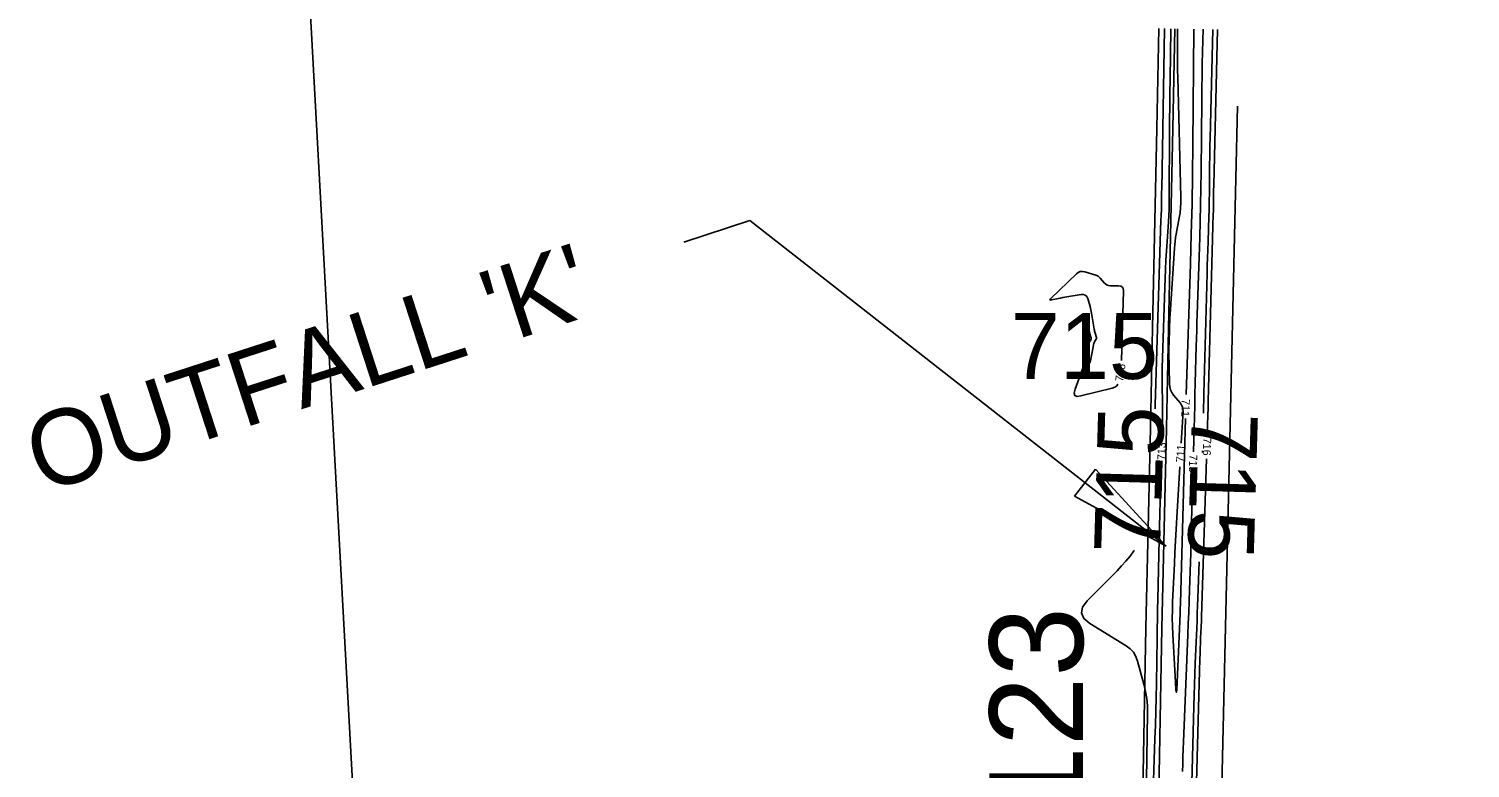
# Model space of a CAD drawing. Extents: x -468563856 to 36492962, y -306094093 to 11899197.
# Drawn here: x 1818576 to 1819296, y 531590 to 531960 of the extents above; entities that cross this region are included whole.
import ezdxf

# ---------------------------------------------------------------- set-up
doc = ezdxf.new("R2010")
doc.units = 0
for name, color, linetype in [('DT_X_Contour_Minor', 7, 'Continuous'), ('DT_X_Terrain_Boundary', 7, 'Continuous'), ('Level 19', 7, 'Continuous'), ('Level 40', 7, 'Continuous'), ('Level 56', 7, 'Continuous'), ('SC_Scratch1', 7, 'Continuous')]:
    doc.layers.add(name, color=color, linetype=linetype)

msp = doc.modelspace()

# ---------------------------------------------------------------- linework, layer by layer
at = {"layer": 'DT_X_Contour_Minor'}
for points in [[(1819138.66, 531769.93), (1819138.65, 531770.63), (1819138.65, 531770.93), (1819138.65, 531771.23), (1819138.66, 531771.53), (1819138.66, 531771.83), (1819141.51, 531864.46), (1819141.53, 531865.12), (1819141.56, 531865.78), (1819141.59, 531866.44), (1819141.63, 531867.1), (1819141.77, 531869.25), (1819141.8, 531869.71), (1819141.82, 531870.17), (1819141.83, 531870.63), (1819141.84, 531871.09), (1819141.85, 531875.68), (1819141.86, 531876.66), (1819141.86, 531877.64), (1819141.88, 531878.62), (1819141.89, 531879.61), (1819143.26, 531960.15)], [(1819142, 531754.87), (1819142.17, 531760.74), (1819142.24, 531763.67), (1819142.28, 531766.6), (1819142.29, 531769.53), (1819142.26, 531772.45), (1819142.13, 531782.02), (1819142.11, 531784.07), (1819142.12, 531786.12), (1819142.15, 531788.17), (1819142.2, 531790.22), (1819143.44, 531830.59), (1819143.6, 531835.12), (1819143.8, 531839.66), (1819144.03, 531844.18), (1819144.31, 531848.71), (1819145.27, 531863.49), (1819145.45, 531866.66), (1819145.58, 531869.83), (1819145.67, 531873.01), (1819145.7, 531876.18), (1819145.81, 531907.73), (1819145.85, 531914.49), (1819145.9, 531921.25), (1819145.98, 531928.02), (1819146.09, 531934.78), (1819146.51, 531959.67), (1819146.51, 531959.94)], [(1819149.84, 531960), (1819149.8, 531949.14), (1819149.8, 531945.84), (1819149.83, 531942.54), (1819149.87, 531939.23), (1819149.94, 531935.93), (1819151.45, 531875.54), (1819151.44, 531873), (1819151.31, 531870.48), (1819151.05, 531867.96), (1819150.65, 531865.45), (1819149.15, 531857.27), (1819148.85, 531855.51), (1819148.61, 531853.75), (1819148.42, 531851.98), (1819148.28, 531850.21), (1819146.13, 531817.29), (1819146.02, 531815.41), (1819145.92, 531813.54), (1819145.84, 531811.66), (1819145.77, 531809.78), (1819145.58, 531803.64), (1819145.55, 531802.32), (1819145.53, 531801.01), (1819145.53, 531799.69), (1819145.54, 531798.38), (1819145.76, 531782.47), (1819145.91, 531780.9), (1819146.31, 531779.42), (1819146.96, 531778.04), (1819147.87, 531776.74), (1819151.24, 531772.67), (1819151.86, 531771.77), (1819152.29, 531770.8), (1819152.52, 531769.76), (1819152.55, 531768.66), (1819151.63, 531752.75)], [(1819154.07, 531777.06), (1819156.25, 531842.45), (1819156.7, 531857.35), (1819157.06, 531872.26), (1819157.32, 531887.16), (1819157.49, 531902.07), (1819157.98, 531959.85)], [(1819157.77, 531748.32), (1819158.08, 531760.02), (1819158.23, 531765.69), (1819158.38, 531771.35), (1819158.53, 531777.01), (1819158.68, 531782.67), (1819159.16, 531801.17), (1819159.27, 531805.14), (1819159.38, 531809.1), (1819159.5, 531813.06), (1819159.63, 531817.02), (1819160.91, 531855.52), (1819161.16, 531863.77), (1819161.36, 531872.02), (1819161.51, 531880.28), (1819161.6, 531888.53), (1819161.9, 531924.54), (1819161.97, 531930.53), (1819162.05, 531936.51), (1819162.16, 531942.49), (1819162.3, 531948.47), (1819162.57, 531959.76)], [(1819162.78, 531767.67), (1819162.86, 531770.9), (1819162.95, 531774.2), (1819163.04, 531777.49), (1819164.6, 531837.59), (1819164.71, 531841.54), (1819164.82, 531845.49), (1819164.94, 531849.43), (1819165.07, 531853.38), (1819165.5, 531866.27), (1819165.58, 531869.03), (1819165.65, 531871.79), (1819165.7, 531874.56), (1819165.73, 531877.32), (1819165.86, 531892.32), (1819165.89, 531895.54), (1819165.94, 531898.75), (1819166, 531901.97), (1819166.07, 531905.18), (1819167.4, 531959.66)], [(1819164.73, 531756.92), (1819164.78, 531758.61), (1819164.84, 531760.74), (1819165.03, 531767.7), (1819165.07, 531769.19), (1819165.11, 531770.68), (1819165.14, 531772.17), (1819165.18, 531773.66), (1819167.47, 531861.28), (1819167.5, 531862.48), (1819167.53, 531863.68), (1819167.57, 531864.88), (1819167.61, 531866.08), (1819167.74, 531870), (1819167.77, 531870.84), (1819167.79, 531871.68), (1819167.8, 531872.52), (1819167.81, 531873.36), (1819167.85, 531877.92), (1819167.86, 531878.9), (1819167.87, 531879.87), (1819167.89, 531880.85), (1819167.91, 531881.83), (1819169.82, 531959.61)], [(1819121.77, 531793.97), (1819122.82, 531828.9), (1819122.7, 531830.01), (1819122.25, 531830.8), (1819121.47, 531831.28), (1819120.36, 531831.44), (1819116.22, 531831.46), (1819115.37, 531831.54), (1819114.6, 531831.8), (1819113.9, 531832.22), (1819113.29, 531832.81), (1819111.16, 531835.28), (1819110.68, 531835.77), (1819110.14, 531836.17), (1819109.55, 531836.5), (1819108.91, 531836.74), (1819103.39, 531838.42), (1819102.25, 531838.63), (1819101.18, 531838.54), (1819100.18, 531838.13), (1819099.25, 531837.43), (1819086.49, 531825.13), (1819086.11, 531824.69), (1819086.05, 531824.42), (1819086.3, 531824.32), (1819086.88, 531824.39)], [(1819086.88, 531824.39), (1819090.31, 531825.09), (1819091.36, 531825.3), (1819092.42, 531825.5), (1819093.47, 531825.69), (1819094.53, 531825.87), (1819101.69, 531827.04), (1819102.82, 531827.07), (1819103.72, 531826.75), (1819104.42, 531826.08), (1819104.89, 531825.05), (1819106.08, 531821.14), (1819106.32, 531820.3), (1819106.53, 531819.45), (1819106.71, 531818.6), (1819106.87, 531817.74), (1819108.17, 531809.81), (1819108.26, 531809.3), (1819108.37, 531808.79), (1819108.48, 531808.28), (1819108.61, 531807.77), (1819109.22, 531805.52), (1819109.23, 531805.47), (1819109.24, 531805.43), (1819109.26, 531805.38), (1819109.27, 531805.33), (1819109.32, 531805.19), (1819109.32, 531805.16), (1819109.32, 531805.13), (1819109.32, 531805.1), (1819109.3, 531805.07), (1819108.34, 531803.34), (1819108.15, 531802.97), (1819107.99, 531802.58), (1819107.87, 531802.18), (1819107.78, 531801.77), (1819106.32, 531793.85), (1819106.17, 531793.32), (1819105.92, 531792.87), (1819105.57, 531792.49), (1819105.12, 531792.19), (1819103.5, 531791.3), (1819103.18, 531791.08), (1819102.91, 531790.83), (1819102.69, 531790.52), (1819102.53, 531790.17), (1819098.57, 531779.66), (1819098.12, 531777.77), (1819098.47, 531776.57), (1819099.61, 531776.09), (1819101.55, 531776.31), (1819117.16, 531780.17), (1819118.42, 531780.65), (1819119.4, 531781.4), (1819119.92, 531782.18)], [(1819104.28, 531801.33), (1819104.21, 531800.82), (1819104.2, 531800.7), (1819104.21, 531800.66), (1819104.25, 531800.69), (1819104.31, 531800.79), (1819106.56, 531804.81), (1819106.62, 531804.94), (1819106.65, 531805.08), (1819106.65, 531805.22), (1819106.62, 531805.37), (1819106.47, 531805.84), (1819106.44, 531805.95), (1819106.41, 531806.05), (1819106.38, 531806.15), (1819106.35, 531806.26), (1819105.41, 531809.75), (1819105.23, 531810.31), (1819105.08, 531810.49), (1819104.97, 531810.28), (1819104.9, 531809.7), (1819104.33, 531801.77), (1819104.32, 531801.66), (1819104.31, 531801.55), (1819104.3, 531801.44), (1819104.28, 531801.33)], [(1819150.93, 531740.77), (1819149.45, 531715.47), (1819149.12, 531709.66), (1819148.81, 531703.86), (1819148.51, 531698.05), (1819148.24, 531692.24), (1819147.36, 531673.27), (1819147.22, 531669.2), (1819147.18, 531665.14), (1819147.25, 531661.07), (1819147.42, 531657.01), (1819148.73, 531633.16), (1819149, 531629.32), (1819149.26, 531628.05), (1819149.49, 531629.33), (1819149.71, 531633.16), (1819151.09, 531667.5), (1819151.11, 531667.98), (1819151.13, 531668.47), (1819151.14, 531668.96), (1819151.16, 531669.45), (1819151.21, 531671.04), (1819151.22, 531671.38), (1819151.23, 531671.72), (1819151.24, 531672.06), (1819151.25, 531672.4), (1819153.72, 531765.06)], [(1819162.26, 531748.1), (1819162.28, 531748.94), (1819162.28, 531748.94)], [(1819137.36, 531568.43), (1819138.54, 531604.73), (1819138.75, 531611.66), (1819138.94, 531618.59), (1819139.09, 531625.52), (1819139.22, 531632.45), (1819139.58, 531655.1), (1819139.67, 531659.95), (1819139.76, 531664.8), (1819139.85, 531669.65), (1819139.95, 531674.5), (1819140.61, 531704.47), (1819140.76, 531710.89), (1819140.92, 531717.31), (1819141.09, 531723.74), (1819141.27, 531730.16), (1819141.64, 531742.87)], [(1819157.17, 531495.03), (1819158.17, 531539.46), (1819158.46, 531551.92), (1819158.77, 531564.38), (1819159.09, 531576.84), (1819159.44, 531589.3), (1819161.01, 531644.73), (1819161.09, 531647.34), (1819161.18, 531649.96), (1819161.27, 531652.58), (1819161.37, 531655.2), (1819161.72, 531663.74), (1819161.79, 531665.58), (1819161.86, 531667.41), (1819161.92, 531669.24), (1819161.98, 531671.07), (1819164.36, 531744.92)], [(1819152.3, 531588.34), (1819152.41, 531592.07), (1819152.54, 531595.79), (1819152.67, 531599.52), (1819152.81, 531603.24), (1819154.97, 531656.78), (1819155.19, 531662.41), (1819155.4, 531668.05), (1819155.6, 531673.68), (1819155.79, 531679.32), (1819156.38, 531697.73), (1819156.5, 531701.68), (1819156.62, 531705.62), (1819156.73, 531709.57), (1819156.84, 531713.52), (1819157.45, 531736.33)], [(1819134.14, 531572.95), (1819134.86, 531617.56), (1819134.79, 531621.23), (1819134.46, 531624.86), (1819133.88, 531628.47), (1819133.03, 531632.04), (1819129.85, 531643.65), (1819128.97, 531646), (1819127.72, 531648.06), (1819126.1, 531649.84), (1819124.09, 531651.34), (1819105.97, 531662.54), (1819102.97, 531665.04), (1819101.75, 531667.75), (1819102.3, 531670.68), (1819104.63, 531673.81), (1819119.6, 531688.89), (1819121.84, 531691.24), (1819124, 531693.67), (1819126.06, 531696.18), (1819128.03, 531698.77), (1819128.25, 531699.07)], [(1819156.88, 531582.58), (1819157.97, 531621.19), (1819158.13, 531626.55), (1819158.31, 531631.9), (1819158.5, 531637.26), (1819158.71, 531642.62), (1819159.42, 531660.12), (1819159.56, 531663.87), (1819159.7, 531667.62), (1819159.83, 531671.37), (1819159.96, 531675.12), (1819160.55, 531693.39)]]:
    msp.add_lwpolyline(points, dxfattribs=at)
at = {"layer": 'DT_X_Terrain_Boundary'}
msp.add_line((1819179.82, 531921.31), (1819158.8, 531007.53), dxfattribs=at)
at = {"layer": 'Level 40'}
for p, q in [((1818902.94, 531853.31), (1818936.05, 531864.06)), ((1819144.18, 531701.16), (1818936.05, 531864.06)), ((1819098.29, 531726.2), (1819108.87, 531739.72)), ((1819108.87, 531739.72), (1819144.18, 531701.16)), ((1819144.18, 531701.16), (1819098.29, 531726.2))]:
    msp.add_line(p, q, dxfattribs=at)
at = {"layer": 'Level 56'}
for points in [[(1819122.25, 531041.53), (1819123.49, 531110.37), (1819125.23, 531210.36), (1819126.4, 531260.35), (1819128.19, 531360.33), (1819129.12, 531410.32), (1819130.49, 531485.11), (1819132.06, 531560.29), (1819134.01, 531660.27), (1819136.23, 531760.25), (1819137.31, 531810.24), (1819139.44, 531910.21), (1819140.49, 531960.2)], [(1819130.25, 531041.36), (1819131.48, 531110.21), (1819133.23, 531210.2), (1819134.4, 531260.18), (1819136.18, 531360.17), (1819137.12, 531410.16), (1819138.49, 531484.95), (1819140.06, 531560.13), (1819142, 531660.11), (1819144.22, 531760.09), (1819145.31, 531810.08), (1819147.43, 531910.05), (1819148.49, 531960.04)]]:
    msp.add_lwpolyline(points, dxfattribs=at)
at = {"layer": 'SC_Scratch1'}
msp.add_lwpolyline([(1818754.73, 531265.42), (1818680.3, 532625.97), (1826365.04, 535120.88), (1826839.27, 533890.33), (1827446.85, 532018.88), (1827532.11, 531348.3), (1819682.53, 528840.07), (1819362.19, 529394.35)], close=True, dxfattribs=at)

# ---------------------------------------------------------------- texts
at = {"layer": 'Level 19'}
msp.add_text('715', height=33, dxfattribs=at).set_placement((1819066.47, 531784.83))
for s, height, rotation, p in [('716', 4, 81.07668, (1819122.52, 531783.28)), ('711', 4, 268.33734, (1819151.99, 531774.77)), ('715', 33, 88.31907, (1819141.03, 531697.07)), ('715', 33, 268.31037, (1819157.05, 531768.52)), ('713', 4, 88.31907, (1819143.68, 531744.14)), ('711', 4, 86.66168, (1819153.06, 531742.99)), ('716', 4, 268.19415, (1819162.69, 531755.45)), ('713', 4, 268.47259, (1819155.73, 531747.05))]:
    msp.add_text(s, height=height, rotation=rotation, dxfattribs=at).set_placement(p)
at = {"layer": 'Level 40'}
for s, height, rotation, p in [("OUTFALL 'K'", 37.5, 17.9864, (1818581.92, 531727.42)), ('C.R. 123', 46.8, 90, (1819102.58, 531423.72))]:
    msp.add_text(s, height=height, rotation=rotation, dxfattribs=at).set_placement(p)

doc.saveas('drawing.dxf')
